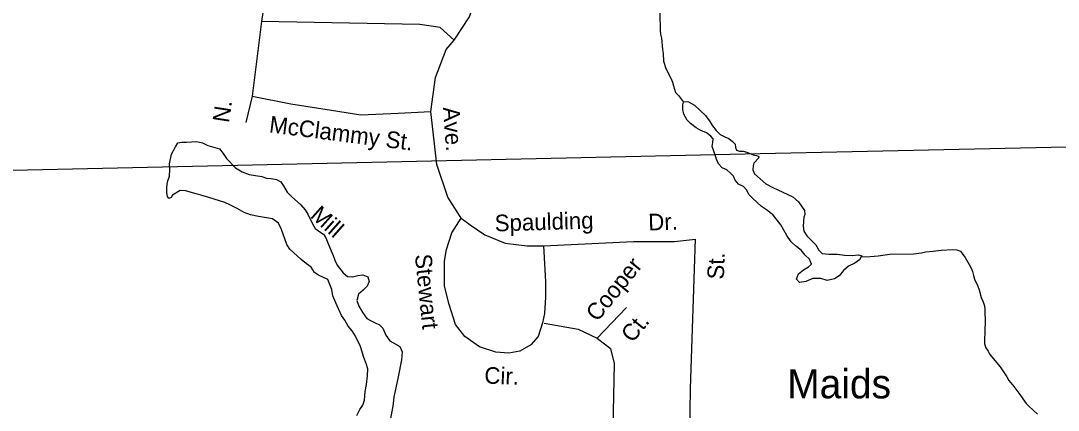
# Model space of a CAD drawing. Extents: x 1945482 to 2853149, y 66427 to 1015778.
# Drawn here: x 2327723 to 2331820, y 183778 to 185314 of the extents above; entities that cross this region are included whole.
import ezdxf

# ---------------------------------------------------------------- set-up
doc = ezdxf.new("R2010")
doc.units = 0
for name, color, linetype in [('Old_Level_10', 7, 'Continuous'), ('Old_Level_19', 7, 'Continuous'), ('Old_Level_21', 7, 'Continuous'), ('Old_Level_35', 7, 'Continuous'), ('Old_Level_56', 7, 'Continuous'), ('Old_Level_59', 7, 'Continuous'), ('Old_Level_60', 7, 'Continuous')]:
    doc.layers.add(name, color=color, linetype=linetype)

msp = doc.modelspace()

# ---------------------------------------------------------------- linework, layer by layer
at = {"layer": 'Old_Level_35'}
msp.add_line((2330351.4, 182912.2), (2330368.1, 183864.6), dxfattribs=at)
for points in [[(2329465, 184532.2), (2329409.8, 184618.1), (2329366.8, 184747), (2329342.3, 184955.7), (2329360.7, 185090.7), (2329403.6, 185201.1), (2329434.3, 185238), (2329495.6, 185330), (2329526.3, 185422.1), (2329507.9, 185790.3), (2329480.2, 186441.1)], [(2328747.4, 185808.7), (2328673.8, 185311.6), (2328637, 185017), (2328612.5, 184912.7)], [(2329434.3, 185238), (2329379.1, 185287.1), (2329299.4, 185299.3), (2328673.8, 185311.6)], [(2328637, 185017), (2328790.3, 184986.3), (2328949.8, 184961.8), (2329066.3, 184943.4), (2329213.5, 184949.5), (2329342.3, 184955.7)], [(2329784.2, 184123.4), (2329766.1, 184068.7), (2329737.1, 184036.1), (2329693.7, 184010.7), (2329650.3, 184003.5), (2329599.7, 184007.1), (2329534.5, 184028.8), (2329476.6, 184068.7), (2329440.4, 184115.8), (2329415.1, 184195.4), (2329397, 184267.9), (2329397, 184365.7), (2329404.3, 184412.7), (2329426, 184477.9), (2329462.2, 184535.9)], [(2329462.2, 184535.9), (2329498.3, 184509.4), (2329556.2, 184469.6), (2329635.8, 184437), (2329722.7, 184426.1), (2329787.8, 184427.2)], [(2329787.8, 184427.2), (2330142.4, 184444.2), (2330305.2, 184444.2), (2330388.4, 184452.2)], [(2330368.1, 183864.6), (2330388.4, 184452.2)], [(2329787.8, 184427.2), (2329795, 184286), (2329795, 184224.4), (2329791.4, 184159.2), (2329784.2, 184123.4)], [(2329999.1, 184062.8), (2330115.1, 184183.6)], [(2329790, 184121), (2329924.9, 184097.7), (2329999.1, 184062.8)], [(2329999.1, 184062.8), (2330051.9, 184022.2), (2330066, 183962.7), (2330047.6, 183072.8)]]:
    msp.add_lwpolyline(points, dxfattribs=at)
at = {"layer": 'Old_Level_56'}
for p, q in [((2330643.1, 184789), (2328520.5, 184741.7)), ((2332017.1, 184819.7), (2330643.1, 184789)), ((2328520.5, 184741.7), (2326380.1, 184694))]:
    msp.add_line(p, q, dxfattribs=at)
at = {"layer": 'Old_Level_59'}
for points in [[(2330246.2, 185413.7), (2330248.5, 185275.8), (2330250.2, 185260.8), (2330253.2, 185246.1), (2330258, 185200.4), (2330260.5, 185185.5), (2330261.5, 185155), (2330270.2, 185125.9), (2330292, 185085.7), (2330297.5, 185071.5), (2330301, 185056.9), (2330309.2, 185031.2), (2330320.2, 185019), (2330340.2, 184993.5)], [(2331042.5, 184382.9), (2331035.5, 184371.6), (2331017.5, 184358.1), (2330992.5, 184345.8), (2330972, 184328.8), (2330954.7, 184308.4), (2330936.5, 184297), (2330908, 184290), (2330882.2, 184297.8), (2330851, 184297.4), (2330823.2, 184285.4), (2330798, 184282.1), (2330786.5, 184295.5), (2330794.5, 184316.4), (2330814, 184332.2), (2330834, 184344.3), (2330845.7, 184354.8), (2330838.2, 184373.9), (2330821.5, 184389.5), (2330804.7, 184408.9), (2330782.7, 184426.6), (2330765.7, 184441.8), (2330748.7, 184467.6), (2330724.5, 184509.3), (2330691.5, 184552), (2330687, 184553.7), (2330667.5, 184568.5), (2330649, 184581.3), (2330613, 184614.1), (2330600, 184628), (2330589, 184646.9), (2330577.2, 184660.6), (2330557.2, 184669.7), (2330545, 184685.9), (2330537.7, 184701.1), (2330526.5, 184712.7), (2330511.7, 184726.8), (2330492.5, 184734.7), (2330478, 184749.4), (2330470.2, 184768.6), (2330459.5, 184803.8), (2330453, 184818.9), (2330456, 184834.1), (2330457, 184848.7), (2330448, 184859.5), (2330431, 184871.7), (2330409, 184881.5), (2330390.5, 184892), (2330368, 184908.8), (2330355.5, 184922.7), (2330347.7, 184934.1), (2330342, 184946.3), (2330338, 184964.3), (2330337.7, 184982.2), (2330340.2, 184993.5)], [(2330340.2, 184993.5), (2330340.7, 184996.3), (2330360.5, 184995), (2330383.5, 184981.8), (2330426.7, 184940.6), (2330441.2, 184921.4), (2330455, 184900), (2330470, 184882), (2330485.5, 184866.2), (2330503.7, 184856.6), (2330519, 184850.1), (2330533.7, 184838.6), (2330544.2, 184827), (2330546.2, 184813.9), (2330549.7, 184803.4), (2330561, 184800.3), (2330575.7, 184799.8), (2330590.7, 184795.9), (2330615.5, 184785.2), (2330629.2, 184783.1), (2330637.5, 184778.2), (2330637, 184771.8), (2330618.5, 184752.7), (2330615.2, 184741.6), (2330614.5, 184726.6), (2330620.2, 184710.4), (2330666, 184670.8), (2330693.5, 184656.6), (2330771.5, 184620.1), (2330794.2, 184600.1), (2330817.7, 184566.3), (2330819.2, 184550), (2330815, 184539.9), (2330812.7, 184504.6), (2330815.5, 184483.8), (2330827.5, 184466.6), (2330844.2, 184448.6), (2330863.2, 184430.3), (2330874.5, 184410), (2330888.5, 184396.8), (2330914.2, 184393.3), (2330946.7, 184393.3), (2330975.7, 184389.6), (2331006, 184387.9), (2331031, 184391.2), (2331044.7, 184386.6), (2331042.5, 184382.9)], [(2331042.5, 184382.9), (2331077.5, 184383.9), (2331108.5, 184387.2), (2331155.7, 184393.5), (2331248.5, 184394.6), (2331279.7, 184399.3), (2331295.5, 184402.6), (2331326.7, 184405.4), (2331357.5, 184410.1), (2331404.2, 184411.9), (2331419.7, 184410.7), (2331434.2, 184405.3), (2331443, 184392.4), (2331452.5, 184380.2), (2331468.5, 184353.2), (2331476, 184338.7), (2331482, 184324.9), (2331485.5, 184309.8), (2331490.2, 184295.5), (2331502.7, 184267.6), (2331508, 184252.6), (2331515.7, 184222.4), (2331522.5, 184208.5), (2331527.7, 184194.3), (2331530.7, 184179.4), (2331531.5, 184117.9), (2331530, 184102.9), (2331528.7, 184039.6), (2331533.7, 184024.3), (2331543, 184011.2), (2331550.7, 183997.6), (2331591.5, 183949.4), (2331617.2, 183910.1), (2331625, 183895.6), (2331644.7, 183871.6), (2331664.7, 183845.5), (2331693.5, 183805.4), (2331704.5, 183794.1), (2331739, 183762.8)]]:
    msp.add_lwpolyline(points, dxfattribs=at)
at = {"layer": 'Old_Level_60'}
for points in [[(2328319, 184787.7), (2328333.7, 184817.1), (2328343.5, 184832.4), (2328359, 184835.4), (2328377.2, 184834.9), (2328416.7, 184838.5), (2328440.5, 184832.7), (2328461.5, 184822.1), (2328507.5, 184809), (2328522.5, 184791.1), (2328536.2, 184770.7), (2328571, 184733.8), (2328597.2, 184718.2), (2328625, 184708.2), (2328675.2, 184699.8), (2328694.2, 184693.1), (2328712.2, 184691.9), (2328733.2, 184688.5), (2328750.7, 184679.3), (2328761.2, 184663.3), (2328775, 184638.2), (2328792.2, 184620.5), (2328829.7, 184587.9), (2328846.2, 184568), (2328857.2, 184551.6), (2328875.2, 184513.3), (2328886, 184495.4), (2328904.2, 184482), (2328918.5, 184473.1), (2328928.5, 184457.6), (2328938, 184431.9), (2328957.2, 184388.6), (2328963.5, 184369.9), (2328972.7, 184350.8), (2328997, 184320.1), (2329013.5, 184306.1), (2329033.7, 184304.6), (2329054.5, 184309.6), (2329074.5, 184312.6), (2329093.2, 184304.2), (2329098.5, 184285.8), (2329091.5, 184268.1), (2329075, 184251.5), (2329057.5, 184236), (2329051, 184210.4), (2329058, 184188), (2329074.2, 184162.4), (2329090.5, 184140.4), (2329106.7, 184130.6), (2329122.7, 184123.5), (2329139.5, 184114.5), (2329153, 184101.4), (2329165.5, 184074.7), (2329181, 184051.4), (2329220, 184029.7), (2329229.5, 184008.5), (2329226.5, 183977.2), (2329214.2, 183909.6), (2329197, 183830.4), (2329192.5, 183794.9), (2329181.5, 183738.8)], [(2329062.5, 183781.2), (2329074, 183798.1), (2329080, 183817.8), (2329083, 183852), (2329088.5, 183880.2), (2329092.2, 183913.4), (2329093.7, 183940.9), (2329087.5, 183962.1), (2329078, 183985.8), (2329065.5, 184029.7), (2329044.5, 184070.2), (2329031.5, 184091.3), (2329016.5, 184110.2), (2329002.7, 184133), (2328990, 184151.5), (2328967, 184201.7), (2328956, 184229.9), (2328951, 184254), (2328936, 184294.1), (2328899, 184310.6), (2328883, 184321.7), (2328869.5, 184342.2), (2328851.2, 184355.8), (2328830.5, 184373), (2328785.7, 184413.1), (2328774.2, 184432.3), (2328752.5, 184490.7), (2328741, 184515.8), (2328717.7, 184532.7), (2328662, 184542.1), (2328630.7, 184548.4), (2328605.7, 184558.5), (2328578.2, 184574), (2328552, 184587.4), (2328529.5, 184597.5), (2328466.5, 184617.7), (2328443.5, 184623.3), (2328415.5, 184632), (2328373.5, 184643.2), (2328353.2, 184644.9), (2328322, 184626.8), (2328316.7, 184617.8), (2328307.5, 184612.9), (2328302.2, 184621.5), (2328300.2, 184637.8), (2328299.7, 184656.9), (2328302.5, 184679.4), (2328310.5, 184701.9), (2328312.5, 184727.8), (2328311, 184749.9), (2328319, 184787.7)], [(2329050.2, 183757.4), (2329062.5, 183781.2)]]:
    msp.add_lwpolyline(points, dxfattribs=at)

# ---------------------------------------------------------------- texts
at = {"layer": 'Old_Level_10'}
for s, height, rotation, p in [('N.', 65.62, 81.2311, (2328545, 184909.5)), ('Ave.', 65.62, 274.261, (2329390.1, 184972.4)), ('McClammy St.', 65.617, 352.7278, (2328701.8, 184874.3)), ('Spaulding', 65.62, 1.7368, (2329595.8, 184483.1)), ('Dr.', 65.62, 1.7368, (2330202, 184486.9)), ('Stewart', 65.62, 275.8211, (2329279.6, 184391.1)), ('Cooper', 65.62, 50.9242, (2330000, 184123.9)), ('St.', 65.62, 87.6998, (2330499.5, 184292.7)), ('Ct.', 65.62, 50.9242, (2330139.1, 184041)), ('Cir.', 65.62, 357.9438, (2329553.1, 183883.5))]:
    msp.add_text(s, height=height, rotation=rotation, dxfattribs=at).set_placement(p)
at = {"layer": 'Old_Level_19'}
msp.add_text('Maids', height=114.83, dxfattribs=at).set_placement((2330750.2, 183825.2))
at = {"layer": 'Old_Level_21'}
msp.add_text('Mill', height=65.62, rotation=318.2752, dxfattribs=at).set_placement((2328863, 184541.5))

doc.saveas('drawing.dxf')
